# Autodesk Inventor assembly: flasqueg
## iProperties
Shininess: 21.0
Length Units: 11269
Angle Units: 11279
Time Units: 11290
Mass Units: 11283
Length Display Precision: 3
Angle Display Precision: 2
Compacted: True
Created: 2001-12
Part Number: flasqueg
Document SubType Name: Assemblage
Designer: pichon
Density: 0.0
Volumn: 0.0
Area: 0.0
PropertySet Name: Model Information
Control State: 0
Master: False
Checked Out: False
Author: pichon
